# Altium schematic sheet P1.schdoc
size 297 x 209 mm; Border: 1; Symbol: Drawing-Symbol_A4; @Project Name: free-dap-programmer; @Page Count: 1; @Update Date: 2026-04-02; @Create Date: 2026-03-31; @Schematic Name: Schematic1; @Page No: 1; @Page Name: P1; Company: EasyEDA.com; Version: V1.0; Page Size: A4; @Create Time: 22:28:50; @Update Time: 18:59:36; Width: 1170; Height: 825; Region Start: 1; X Region Count: 6; Y Region Count: 4; Blade Width: 10; Title Block Position: 3; @Board Name: Board1; Device: Drawing-Symbol_A4
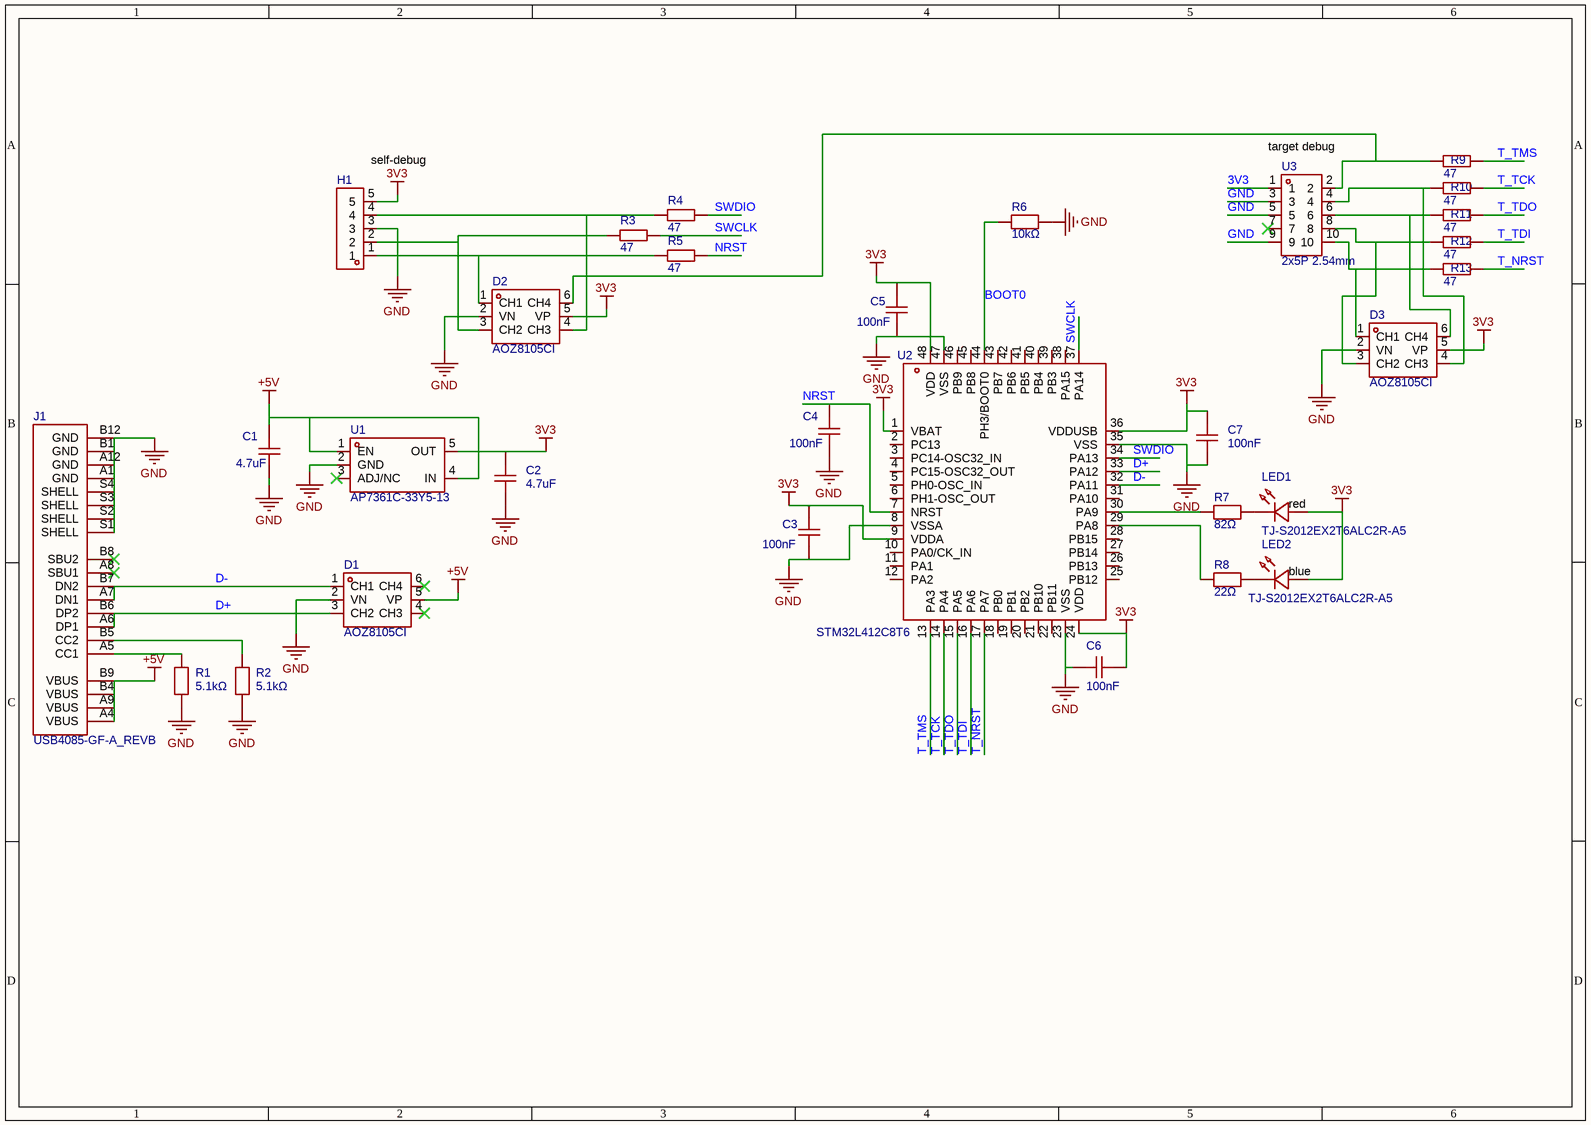
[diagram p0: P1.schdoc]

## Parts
C1  4.7uF  [0805]
C2  4.7uF  [C0805]
C3  100nF  [C0805]
C4  100nF  [C0805]
C5  100nF  [C0805]
C6  100nF  [C0805]
C7  100nF  [C0805]
D1  AOZ8105CI  [TSOT-23-6_L2.9-W1.6-P0.95-LS2.8-BR]
D2  AOZ8105CI  [TSOT-23-6_L2.9-W1.6-P0.95-LS2.8-BR]
D3  AOZ8105CI  [TSOT-23-6_L2.9-W1.6-P0.95-LS2.8-BR]
H1  800-10-005-10-001000  [HDR-TH_800-10-005-66-001101]  (value not drawn)
J1  USB4085-GF-A_REVB  [GCT_USB4085-GF-A_REVB]
LED1  TJ-S2012EX2T6ALC2R-A5  [LED0805-RD]
LED2  TJ-S2012EX2T6ALC2R-A5  [LED0805-RD]
R1  5.1kΩ  [0805]
R2  5.1kΩ  [0805]
R3  47  [R0805]
R4  47  [R0805]
R5  47  [R0805]
R6  10kΩ  [0805]
R7  82Ω  [0805]
R8  22Ω  [0805]
R9  47  [R0805]
R10  47  [R0805]
R11  47  [R0805]
R12  47  [R0805]
R13  47  [R0805]
U1  AP7361C-33Y5-13  [SOT-89-5_L4.5-W2.5-P1.50-LS4.5-BR]
U2  STM32L412C8T6  [LQFP-48_L7.0-W7.0-P0.50-LS9.0-BL]
U3  2x5P 2.54mm  [HDR-TH_10P-P2.54-V-F-R2-C5-S2.54-1]

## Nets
3V3: C2.2 C3.1 C5.1 C6.1 C7.1 D2.5(VP) D3.5(VP) H1.5 LED1.2(A) LED2.2(A) U1.5(OUT) U2.1(VBAT) U2.9(VDDA) U2.24(VDD) U2.36(VDDUSB) U2.48(VDD) U3.1
+5V: C1.1 D1.5(VP) J1.A4(VBUS) J1.A9(VBUS) J1.B4(VBUS) J1.B9(VBUS) U1.1(EN) U1.4(IN)
GND: C1.2 C2.1 C3.2 C4.2 C5.2 C6.2 C7.2 D1.2(VN) D2.2(VN) D3.2(VN) H1.3 J1.A1(GND) J1.A12(GND) J1.B1(GND) J1.B12(GND) J1.S1(SHELL) J1.S2(SHELL) J1.S3(SHELL) J1.S4(SHELL) R1.1 R2.1 R6.1 U1.2(GND) U2.8(VSSA) U2.23(VSS) U2.35(VSS) U2.47(VSS) U3.3 U3.5 U3.9
BOOT0: R6.2 U2.44(PH3/BOOT0)
D+: D1.3(CH2) J1.A6(DP1) J1.B6(DP2) U2.33(PA12)
D-: D1.1(CH1) J1.A7(DN1) J1.B7(DN2) U2.32(PA11)
NRST: C4.1 R5.2 U2.7(NRST)
SWCLK: R3.2 U2.37(PA14)
SWDIO: R4.2 U2.34(PA13)
T_NRST: R13.2 U2.17(PA7)
T_TCK: R10.2 U2.14(PA4)
T_TDI: R12.2 U2.16(PA6)
T_TDO: R11.2 U2.15(PA5)
T_TMS: R9.2 U2.13(PA3)
NetD2_1: D2.1(CH1) H1.1 R5.1
NetD2_3: D2.3(CH2) H1.2 R3.1
NetD2_4: D2.4(CH3) H1.4 R4.1
NetD2_6: D2.6(CH4) R9.1 U3.2
NetD3_1: D3.1(CH1) R13.1 U3.10
NetD3_3: D3.3(CH2) R12.1 U3.8
NetD3_4: D3.4(CH3) R10.1 U3.4
NetD3_6: D3.6(CH4) R11.1 U3.6
NetJ1_A5: J1.A5(CC1) R1.2
NetJ1_B5: J1.B5(CC2) R2.2
NetLED1_1: LED1.1(C) R7.2
NetLED2_1: LED2.1(C) R8.2
NetR7_1: R7.1 U2.30(PA9)
NetR8_1: R8.1 U2.29(PA8)

Not connected (* = marked no-connect by the designer): D1 4(CH3)* 6(CH4)*; J1 A8(SBU1)* B8(SBU2)*; U1 3(ADJ/NC)*; U2 2(PC13) 3(PC14-OSC32_IN) 4(PC15-OSC32_OUT) 5(PH0-OSC_IN) 6(PH1-OSC_OUT) 10(PA0/CK_IN) 11(PA1) 12(PA2) 18(PB0) 19(PB1) 20(PB2) 21(PB10) 22(PB11) 25(PB12) 26(PB13) 27(PB14) 28(PB15) 31(PA10) 38(PA15) 39(PB3) 40(PB4) 41(PB5) 42(PB6) 43(PB7) 45(PB8) 46(PB9); U3 7*

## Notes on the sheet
- (near H1) self-debug
- (near U3) target debug
- (near LED1) red
- (near LED2) blue

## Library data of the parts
C1 = C0805-100nF: Capacitance:100nF Tolerance:±10% Tolerance:±10% Voltage Rating:50V Temperature Coefficient:X7R; Manufacturer: YAGEO(国巨); Manufacturer Part: CC0805KRX7R9BB104; 3D Model: 8c88e81f49c6409b980720ec8953afb6; 3D Model Transform: 78.74,51.181,0,0,0,0,0,0.0005,0; Tolerance: ±10%; Voltage Rating: 50V; Temperature Coefficient: X7R; AddInBom: yes; ModelName: C0805_L2.0-W1.3-H1.3
C2-C7 = CGA0805X5R475M500MT: Capacitance:4.7uF Tolerance:±20% Tolerance:±20% Voltage Rating:50V Temperature Coefficient:X5R; Manufacturer: HRE(芯声); 3D Model: 8c88e81f49c6409b980720ec8953afb60819f05c4eef4c71ace90d822a990e87; 3D Model Transform: 78.74,51.181,0,0,0,0,0,0.0005,0; Tolerance: ±20%; Voltage Rating: 50V; Temperature Coefficient: X5R; AddInBom: yes; ModelName: C0805_L2.0-W1.3-H1.3
D1-D3 = AOZ8105CI: Reverse Stand-Off Voltage (Vrwm):5V Maximum Clamping Voltage:16.5V Peak Pulse Current (Ipp):5A Peak Pulse Power Dissipation (Ppp):- Breakdown Voltage:6.6V Number of Lines:Four channels Operating Temperature:-40℃~+125℃@(Tj) Operating Temperature:-40℃~+125℃; Manufacturer: AOS; AddInBom: yes; ModelId: b82f856f33de448a91344795012188a20819f05c4eef4c71ace90d822a990e87; ModelName: TSOT-23-6_L2.9-W1.6-H1.1-LS2.8-P0.95; ModelTransform: 110.45568,114.173,0,180,0,0,-0.005,-0.0005,0; Reverse Stand-Off Voltage (Vrwm): 5V; Maximum Clamping Voltage: 16.5V; Peak Pulse Current (Ipp): 5A; Breakdown Voltage: 6.6V; Type: ESD
H1 = 800-10-005-10-001000: Pitch:2.54mm Mounting Type:Through Hole Number of Rows:1 Number of Pins:5P Contact Material:Brass alloy Contact Plating:Gold Color:Black; Manufacturer: Mill-Max Mfg. Corp.; 3D Model: 13b1d1e9c1e2408a9a5fa669a7b049ec0819f05c4eef4c71ace90d822a990e87; 3D Model Transform: 500.393,100,0,0,0,0,0,0,-149.606; Pitch: 2.54mm; AddInBom: yes
J1 = USB4085-GF-A_REVB: MF: Global Connector Technology; Package1: None; VENDOR: GCT; AddInBom: yes
LED1 LED2 = TJ-S2012EX2T6ALC2R-A5: Illumination Color:Red Voltage - Forward(Vf):1.8V~2.4V Voltage - Forward(Vf):1.8V~2.4V Power(Watts):48mW Forward Current:20mA Wavelength - Dominant:620nm~630nm Wavelength - Dominant:620nm~630nm Peak Wavelength:631nm Luminous Intensity:500mcd Luminous Inte; Manufacturer: TOGIALED(统佳); AddInBom: yes; ModelId: 23093642268545519703b953fc993978; ModelTransform: 79.527,49.2125,0,0,0,0,0,0,0; Illumination Color: Red; Power(Watts): 48mW; Forward Current: 20mA; Peak Wavelength: 631nm; Luminous Intensity: 500mcd; Viewing Angle: 60°
R1 R2 R6-R8 = MCU08050C1003FP500: Type:Thin Film Resistor Resistance:100kΩ Tolerance:±1% Tolerance:±1% Power(Watts):200mW Voltage-Supply(Max):150V Temperature Coefficient:±50ppm/℃ Temperature Coefficient:±50ppm/℃ Operating Temperature:-55℃~+155℃ Operating Temperature:-55℃~+155℃; Manufacturer: VISHAY(威世); 3D Model: b83c7c5430874b8eb2319a65d94334290819f05c4eef4c71ace90d822a990e87; 3D Model Transform: 78.74,51.181,0,0,0,0,0,-0.0005,0; Tolerance: ±1%; Power(Watts): 200mW; Voltage-Supply(Max): 150V; AddInBom: yes; ModelName: R0805_L2.0-W1.3-H0.6
R3-R5 R9-R13 = 10K 0805: Type:Thick Film Resistor Resistance:10kΩ Tolerance:±1% Tolerance:±1% Power(Watts):125mW Voltage-Supply(Max):150V Temperature Coefficient:±100ppm/℃ Temperature Coefficient:±100ppm/℃ Operating Temperature:-55℃~+155℃ Operating Temperature:-55℃~+155℃; Manufacturer: UNI-ROYAL(厚声); Manufacturer Part: 0805W8F1002T5E; 3D Model: b83c7c5430874b8eb2319a65d9433429; 3D Model Transform: 78.74,51.181,0,0,0,0,0,-0.0005,0; Tolerance: ±1%; Power(Watts): 125mW; Voltage-Supply(Max): 150V; AddInBom: yes; ModelName: R0805_L2.0-W1.3-H0.6
U1 = AP7361C-33Y5-13: 输出类型:固定;最大输入电压:6V;输出电压:3.3V;输出电流:1A;电源纹波抑制比(PSRR):75dB@(1kHz)；55dB@(10kHz);输出极性:正极;; Manufacturer: DIODES(美台); 3D Model: 5d1143e2059e472f864aea4034d4850f55fa322f812d4f3bbbcb0c18ed66441c; 3D Model Transform: 177.83067,177.165,0,180,0,0,0,0.0055,0; Output Type: 固定; Maximum Input Voltage: 6V; Output Voltage: 3.3V; Output Current: 1A; Dropout Voltage: 360mV@(1A); standby current: 80uA; Output Polarity: 正极; Number of Outputs: 1; AddInBom: yes; ModelName: SOT-89-5_L4.5-W2.5-H1.5-LS4.1-P1.50
U2 = STM32L412C8T6: CPU Core:ARM-M4 CPU Maximum Speed:80MHz Program Storage Size:64KB Program Memory Type:FLASH Number of I/O:38 ADC (Bit):12bit Low Voltage Detection Threshold:1.71V~3.6V Low Voltage Detection Threshold:1.71V~3.6V Application Area:-; Manufacturer: ST(意法半导体); AddInBom: yes; ModelId: e34e8eb637af47bfa8fcd5196dad09e9; ModelName: LQFP-48_L7.0-W7.0-H1.4-LS9.0-P0.50; ModelTransform: 354.331,354.331,0,0,0,0,0,0,0; CPU Core: ARM-M4; CPU Maximum Speed: 80MHz; Program Storage Size: 64KB; Program Memory Type: FLASH; Number of I/O: 38; ADC (Bit): 12bit
U3 = 2x5P 2.54mm: AddInBom: yes; ModelId: c92ed4b8e8c6446a8ab365472f37d920; ModelName: HDR-F-2.54_2x5; ModelTransform: 519.685,207.874,0,0,0,0,0,0,-118.11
